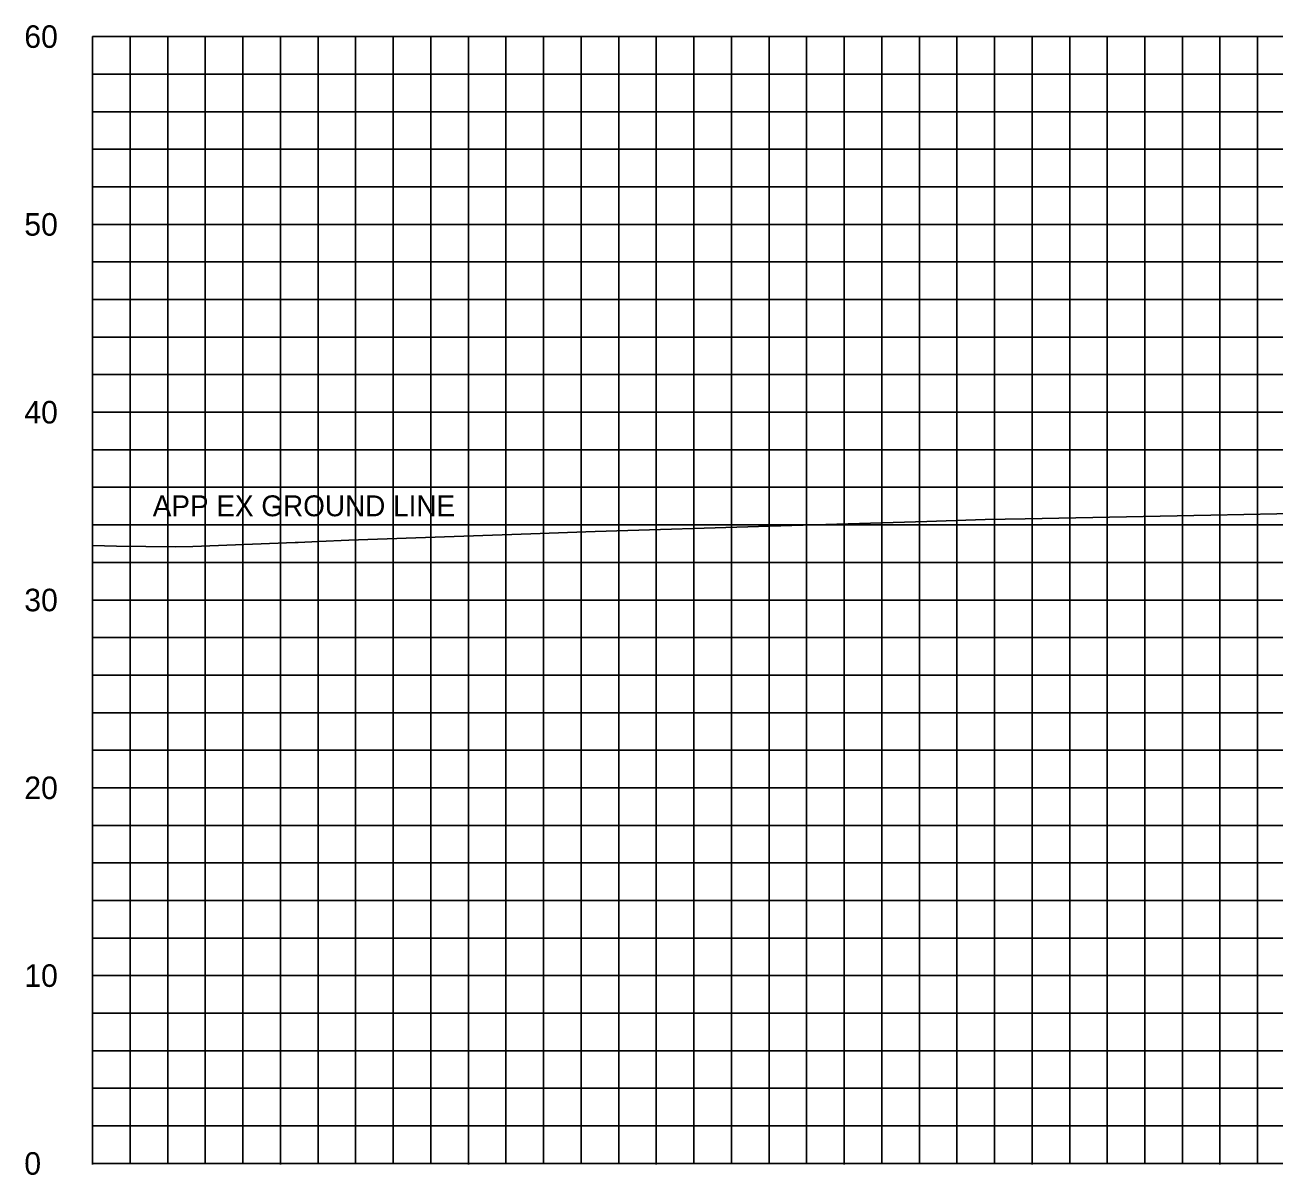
# Model space of a CAD drawing. Extents: x 2193008 to 2198143, y 1236112 to 1237864.
# Drawn here: x 2194694.1 to 2194760.6, y 1237162.5 to 1237223.7 of the extents above; entities that cross this region are included whole.
import ezdxf

# ---------------------------------------------------------------- set-up
doc = ezdxf.new("R2010")
doc.units = 0
for name, color, linetype in [('31', 7, 'Continuous'), ('60', 7, 'Continuous'), ('Level 55', 7, 'Continuous'), ('M-ROADS', 7, 'Continuous')]:
    doc.layers.add(name, color=color, linetype=linetype)

msp = doc.modelspace()

# ---------------------------------------------------------------- linework, layer by layer
at = {"layer": '60'}
for p, q in [((2194697.688, 1237163.106), (2194697.688, 1237223.106)), ((2194697.688, 1237163.046), (2194697.688, 1237163.106)), ((2194697.688, 1237163.106), (2194827.688, 1237163.106)), ((2194707.688, 1237163.046), (2194707.688, 1237163.106)), ((2194717.688, 1237163.046), (2194717.688, 1237163.106)), ((2194727.688, 1237163.046), (2194727.688, 1237163.106)), ((2194737.688, 1237163.046), (2194737.688, 1237163.106)), ((2194747.688, 1237163.046), (2194747.688, 1237163.106)), ((2194757.688, 1237163.046), (2194757.688, 1237163.106))]:
    msp.add_line(p, q, dxfattribs=at)
at = {"layer": 'M-ROADS'}
for p, q in [((2194697.688, 1237223.106), (2194827.688, 1237223.106)), ((2194699.688, 1237163.106), (2194699.688, 1237223.106)), ((2194701.688, 1237163.106), (2194701.688, 1237223.106)), ((2194703.688, 1237163.106), (2194703.688, 1237223.106)), ((2194705.688, 1237163.106), (2194705.688, 1237223.106)), ((2194707.688, 1237163.106), (2194707.688, 1237223.106)), ((2194709.688, 1237163.106), (2194709.688, 1237223.106)), ((2194711.688, 1237163.106), (2194711.688, 1237223.106)), ((2194713.688, 1237163.106), (2194713.688, 1237223.106)), ((2194715.688, 1237163.106), (2194715.688, 1237223.106)), ((2194717.688, 1237163.106), (2194717.688, 1237223.106)), ((2194719.688, 1237163.106), (2194719.688, 1237223.106)), ((2194721.688, 1237163.106), (2194721.688, 1237223.106)), ((2194723.688, 1237163.106), (2194723.688, 1237223.106)), ((2194725.688, 1237163.106), (2194725.688, 1237223.106)), ((2194727.688, 1237163.106), (2194727.688, 1237223.106)), ((2194729.688, 1237163.106), (2194729.688, 1237223.106)), ((2194731.688, 1237163.106), (2194731.688, 1237223.106)), ((2194733.688, 1237163.106), (2194733.688, 1237223.106)), ((2194735.688, 1237163.106), (2194735.688, 1237223.106)), ((2194737.688, 1237163.106), (2194737.688, 1237223.106)), ((2194739.688, 1237163.106), (2194739.688, 1237223.106)), ((2194741.688, 1237163.106), (2194741.688, 1237223.106)), ((2194743.688, 1237163.106), (2194743.688, 1237223.106)), ((2194745.688, 1237163.106), (2194745.688, 1237223.106)), ((2194747.688, 1237163.106), (2194747.688, 1237223.106)), ((2194749.688, 1237163.106), (2194749.688, 1237223.106)), ((2194751.688, 1237163.106), (2194751.688, 1237223.106)), ((2194753.688, 1237163.106), (2194753.688, 1237223.106)), ((2194755.688, 1237163.106), (2194755.688, 1237223.106)), ((2194757.688, 1237163.106), (2194757.688, 1237223.106)), ((2194759.688, 1237163.106), (2194759.688, 1237223.106)), ((2194697.688, 1237221.106), (2194827.688, 1237221.106)), ((2194697.688, 1237219.106), (2194827.688, 1237219.106)), ((2194697.688, 1237217.106), (2194827.688, 1237217.106)), ((2194697.688, 1237215.106), (2194827.688, 1237215.106)), ((2194697.688, 1237213.106), (2194827.688, 1237213.106)), ((2194697.688, 1237211.106), (2194827.688, 1237211.106)), ((2194697.688, 1237209.106), (2194827.688, 1237209.106)), ((2194697.688, 1237207.106), (2194827.688, 1237207.106)), ((2194697.688, 1237205.106), (2194827.688, 1237205.106)), ((2194697.688, 1237203.106), (2194827.688, 1237203.106)), ((2194697.688, 1237201.106), (2194827.688, 1237201.106)), ((2194697.688, 1237199.106), (2194827.688, 1237199.106)), ((2194697.688, 1237197.106), (2194827.688, 1237197.106)), ((2194697.688, 1237195.106), (2194827.688, 1237195.106)), ((2194697.688, 1237193.106), (2194827.688, 1237193.106)), ((2194697.688, 1237191.106), (2194827.688, 1237191.106)), ((2194697.688, 1237189.106), (2194827.688, 1237189.106)), ((2194697.688, 1237187.106), (2194827.688, 1237187.106)), ((2194697.688, 1237185.106), (2194827.688, 1237185.106)), ((2194697.688, 1237183.106), (2194827.688, 1237183.106)), ((2194697.688, 1237181.106), (2194827.688, 1237181.106)), ((2194697.688, 1237179.106), (2194827.688, 1237179.106)), ((2194697.688, 1237177.106), (2194827.688, 1237177.106)), ((2194697.688, 1237175.106), (2194827.688, 1237175.106)), ((2194697.688, 1237173.106), (2194827.688, 1237173.106)), ((2194697.688, 1237171.106), (2194827.688, 1237171.106)), ((2194697.688, 1237169.106), (2194827.688, 1237169.106)), ((2194697.688, 1237167.106), (2194827.688, 1237167.106)), ((2194697.688, 1237165.106), (2194827.688, 1237165.106)), ((2194697.688, 1237163.106), (2194827.688, 1237163.106))]:
    msp.add_line(p, q, dxfattribs=at)
msp.add_lwpolyline([(2194697.688, 1237196.001), (2194698.963, 1237195.979), (2194702.089, 1237195.929), (2194703.022, 1237195.964), (2194708.467, 1237196.16), (2194708.636, 1237196.168), (2194709.717, 1237196.229), (2194711.327, 1237196.286), (2194721.003, 1237196.638), (2194724.434, 1237196.747), (2194733.707, 1237197.046), (2194742.078, 1237197.294), (2194745.19, 1237197.386), (2194747.315, 1237197.427), (2194757.204, 1237197.616), (2194762.472, 1237197.736)], dxfattribs=at)

# ---------------------------------------------------------------- texts
at = {"layer": '31'}
for s, p in [('60', (2194694.054, 1237222.506)), ('50', (2194694.054, 1237212.506)), ('40', (2194694.054, 1237202.506)), ('30', (2194694.054, 1237192.506)), ('20', (2194694.054, 1237182.506)), ('10', (2194694.054, 1237172.506)), ('0', (2194694.054, 1237162.506))]:
    msp.add_text(s, height=1.2, dxfattribs=at).set_placement(p)
at = {"layer": 'Level 55'}
msp.add_text('APP EX GROUND LINE', height=1.11046, dxfattribs=at).set_placement((2194700.891, 1237197.566))

doc.saveas('drawing.dxf')
